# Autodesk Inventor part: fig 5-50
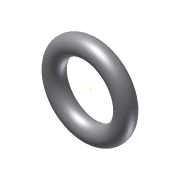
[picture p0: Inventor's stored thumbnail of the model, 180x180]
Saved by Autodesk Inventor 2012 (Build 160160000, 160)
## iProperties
Created: 2010-02
Part Number: fig 5-50
Document SubType Name: Modeling
Designer: CADSoft
Density: 1 g/cm^3
Material: Default
Author: CADSoft
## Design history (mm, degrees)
sketch "Sketch1"
  geometry: L1 (0, 21.37)-(0, -16.247); C1 r 5 at (20.026, 0); 1 further point
  constraints: 2 end point, 1 centre point
  dimensions: "d0" = 10 diameter of C1
revolve "Revolution1" sketch "Sketch1" stored, may be unused: angle "d1" = 90 deg
workpoint "Work Point1"
body "Solid1"
